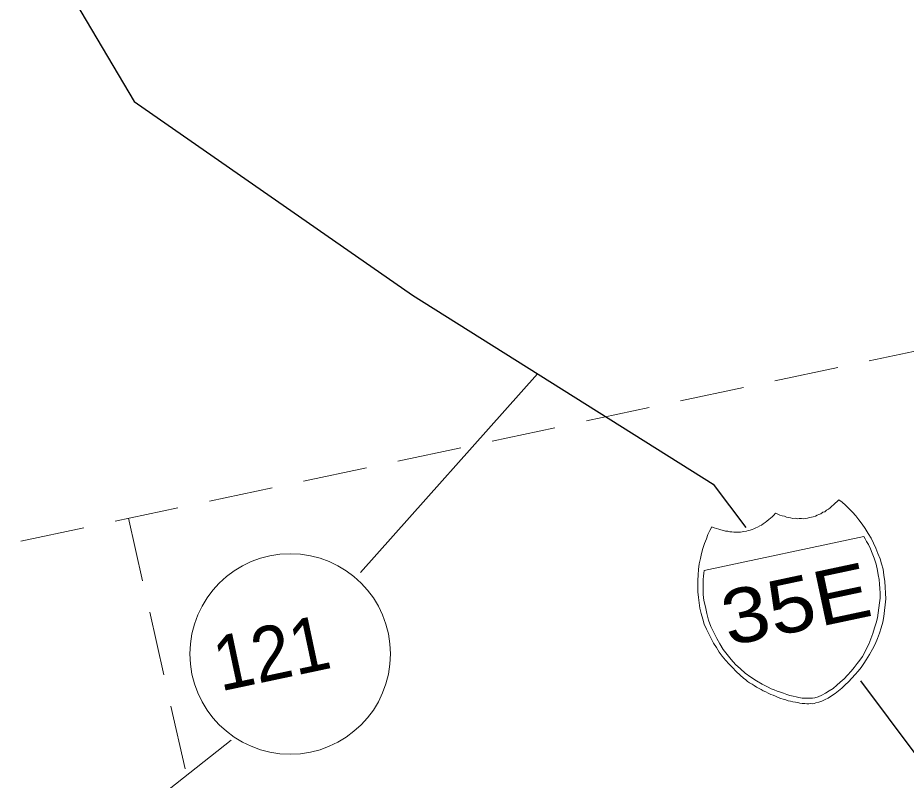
# Model space of a CAD drawing. Extents: x 2357218 to 2371708, y 6973728 to 6980157.
# Drawn here: x 2357598.1 to 2357681, y 6974819.3 to 6974890.5 of the extents above; entities that cross this region are included whole.
import ezdxf

# ---------------------------------------------------------------- set-up
doc = ezdxf.new("R2010")
doc.units = 0
doc.header["$LTSCALE"] = 2
doc.linetypes.add('MEDIUM_DASHED', pattern=[4.5, 3, -1.5])
doc.layers.add('62', color=7, linetype='Continuous', lineweight=13)
doc.layers.add('63', color=7, linetype='Continuous', lineweight=13)

msp = doc.modelspace()

# ---------------------------------------------------------------- linework, layer by layer
at = {"layer": '62', "linetype": 'MEDIUM_DASHED'}
for p, q in [((2357701.055, 6974863.476), (2357262.587, 6974770.278)), ((2357608.391, 6974843.78), (2357670.463, 6974569.716))]:
    msp.add_line(p, q, dxfattribs=at)
at = {"layer": '62'}
msp.add_line((2357630.08, 6974838.706), (2357646.606, 6974857.286), dxfattribs=at)
at = {"layer": '62', "lineweight": 25}
for points in [[(2357578.331, 6974934.355), (2357589.96, 6974914.697), (2357608.93, 6974882.704), (2357634.925, 6974864.627), (2357663.018, 6974846.971), (2357666.063, 6974842.928)], [(2357676.771, 6974828.593), (2357689.879, 6974811.067), (2357705.075, 6974777.351), (2357725.526, 6974754.738)]]:
    msp.add_lwpolyline(points, dxfattribs=at)
at = {"layer": '62'}
for points in [[(2357669.661, 6974843.969), (2357669.858, 6974843.896), (2357670.077, 6974843.85), (2357670.245, 6974843.817), (2357670.462, 6974843.771), (2357670.664, 6974843.789), (2357670.859, 6974843.739), (2357671.039, 6974843.756), (2357671.247, 6974843.752), (2357671.434, 6974843.747), (2357671.636, 6974843.766), (2357671.812, 6974843.804), (2357672.01, 6974843.845), (2357672.184, 6974843.882), (2357672.362, 6974843.92), (2357672.576, 6974843.99), (2357672.721, 6974844.067), (2357672.888, 6974844.148), (2357673.081, 6974844.213), (2357673.262, 6974844.341), (2357673.433, 6974844.402), (2357673.612, 6974844.532), (2357673.776, 6974844.635), (2357673.931, 6974844.762), (2357674.084, 6974844.909), (2357674.244, 6974845.035), (2357674.416, 6974845.185), (2357674.59, 6974845.337), (2357674.738, 6974845.508), (2357675.063, 6974845.278), (2357675.374, 6974844.999), (2357675.693, 6974844.697), (2357676.02, 6974844.354), (2357676.323, 6974844.005), (2357676.631, 6974843.632), (2357676.925, 6974843.234), (2357677.217, 6974842.837), (2357677.499, 6974842.367), (2357677.754, 6974841.938), (2357677.991, 6974841.46), (2357678.209, 6974840.979), (2357678.405, 6974840.491), (2357678.601, 6974840.003), (2357678.726, 6974839.522), (2357678.876, 6974839.026), (2357678.948, 6974838.467), (2357679.05, 6974837.889), (2357679.074, 6974837.342), (2357679.122, 6974836.8), (2357679.145, 6974836.252), (2357679.081, 6974835.686), (2357679.029, 6974835.168), (2357678.961, 6974834.624), (2357678.843, 6974834.094), (2357678.703, 6974833.558), (2357678.535, 6974833.061), (2357678.364, 6974832.566), (2357678.132, 6974832.033), (2357677.892, 6974831.545), (2357677.624, 6974831.074), (2357677.316, 6974830.57), (2357677.091, 6974830.225), (2357676.847, 6974829.85), (2357676.551, 6974829.512), (2357676.277, 6974829.178), (2357675.961, 6974828.834), (2357675.639, 6974828.512), (2357675.332, 6974828.216), (2357675.026, 6974827.923), (2357674.712, 6974827.673), (2357674.397, 6974827.422), (2357674.078, 6974827.192), (2357673.752, 6974826.984), (2357673.458, 6974826.854), (2357673.17, 6974826.699), (2357672.872, 6974826.591), (2357672.606, 6974826.534)], [(2357672.606, 6974826.534), (2357672.43, 6974826.497), (2357672.278, 6974826.463), (2357672.092, 6974826.47), (2357671.933, 6974826.458), (2357671.748, 6974826.466), (2357671.562, 6974826.474), (2357671.329, 6974826.492), (2357671.117, 6974826.516), (2357670.92, 6974826.567), (2357670.704, 6974826.613), (2357670.465, 6974826.653), (2357670.248, 6974826.699), (2357670.008, 6974826.741), (2357669.811, 6974826.813), (2357669.564, 6974826.899), (2357669.319, 6974826.963), (2357669.092, 6974827.053), (2357668.84, 6974827.161), (2357668.614, 6974827.25), (2357668.387, 6974827.338), (2357668.156, 6974827.452), (2357667.919, 6974827.585), (2357667.696, 6974827.676), (2357667.485, 6974827.791), (2357667.254, 6974827.904), (2357667.046, 6974828.02), (2357666.832, 6974828.159), (2357666.64, 6974828.302), (2357666.41, 6974828.415), (2357666.223, 6974828.534), (2357666.052, 6974828.682), (2357665.857, 6974828.849), (2357665.519, 6974829.143), (2357665.147, 6974829.48), (2357664.817, 6974829.847), (2357664.495, 6974830.17), (2357664.164, 6974830.536), (2357663.856, 6974830.906), (2357663.567, 6974831.284), (2357663.314, 6974831.713), (2357663.047, 6974832.114), (2357662.816, 6974832.55), (2357662.607, 6974832.99), (2357662.4, 6974833.43), (2357662.185, 6974833.89), (2357662.039, 6974834.365), (2357661.882, 6974834.885), (2357661.753, 6974835.385), (2357661.69, 6974835.901), (2357661.63, 6974836.395), (2357661.589, 6974836.916), (2357661.569, 6974837.442), (2357661.572, 6974837.97), (2357661.597, 6974838.505), (2357661.651, 6974838.999), (2357661.7, 6974839.539), (2357661.826, 6974840.025), (2357661.932, 6974840.508), (2357662.06, 6974840.971), (2357662.197, 6974841.416), (2357662.377, 6974841.868), (2357662.499, 6974842.262), (2357662.694, 6974842.647), (2357662.896, 6974842.991), (2357663.103, 6974842.896), (2357663.322, 6974842.827), (2357663.545, 6974842.761), (2357663.739, 6974842.71), (2357663.961, 6974842.64), (2357664.155, 6974842.592), (2357664.367, 6974842.567), (2357664.561, 6974842.517), (2357664.742, 6974842.533), (2357664.937, 6974842.482), (2357665.141, 6974842.501), (2357665.329, 6974842.494), (2357665.557, 6974842.498), (2357665.714, 6974842.508), (2357665.89, 6974842.546), (2357666.112, 6974842.593), (2357666.288, 6974842.63), (2357666.464, 6974842.667), (2357666.658, 6974842.732), (2357666.823, 6974842.813), (2357666.988, 6974842.893), (2357667.161, 6974842.955), (2357667.364, 6974843.09), (2357667.535, 6974843.149), (2357667.693, 6974843.272), (2357667.854, 6974843.378), (2357668.036, 6974843.507), (2357668.207, 6974843.66), (2357668.365, 6974843.785), (2357668.52, 6974843.933), (2357668.67, 6974844.08), (2357668.84, 6974844.254), (2357669.044, 6974844.159), (2357669.245, 6974844.087), (2357669.466, 6974844.019), (2357669.661, 6974843.969)], [(2357587.853, 6974800.146), (2357596.85, 6974808.683), (2357603.892, 6974811.906), (2357617.998, 6974823.047)]]:
    msp.add_lwpolyline(points, dxfattribs=at)
msp.add_lwpolyline([(2357677.08, 6974842.072), (2357662.176, 6974838.904), (2357662.137, 6974838.666), (2357662.106, 6974838.382), (2357662.083, 6974838.056), (2357662.084, 6974837.618), (2357662.068, 6974837.155), (2357662.082, 6974836.653), (2357662.154, 6974836.095), (2357662.283, 6974835.499), (2357662.41, 6974834.882), (2357662.588, 6974834.276), (2357662.807, 6974833.677), (2357663.064, 6974833.111), (2357663.341, 6974832.569), (2357663.634, 6974832.055), (2357663.953, 6974831.527), (2357664.332, 6974831.054), (2357664.706, 6974830.583), (2357665.099, 6974830.138), (2357665.554, 6974829.728), (2357666.009, 6974829.319), (2357666.526, 6974828.946), (2357667.06, 6974828.599), (2357667.586, 6974828.295), (2357668.153, 6974828.003), (2357668.417, 6974827.852), (2357668.715, 6974827.755), (2357668.993, 6974827.63), (2357669.312, 6974827.537), (2357669.587, 6974827.434), (2357669.889, 6974827.312), (2357670.181, 6974827.238), (2357670.473, 6974827.162), (2357670.76, 6974827.109), (2357671.027, 6974827.049), (2357671.312, 6974826.994), (2357671.549, 6974826.977), (2357671.825, 6974826.967), (2357672.054, 6974826.968), (2357672.284, 6974826.971), (2357672.508, 6974826.997), (2357672.806, 6974827.106), (2357673.168, 6974827.25), (2357673.496, 6974827.437), (2357673.861, 6974827.674), (2357674.206, 6974827.885), (2357674.554, 6974828.191), (2357674.883, 6974828.49), (2357675.233, 6974828.796), (2357675.573, 6974829.142), (2357675.887, 6974829.509), (2357676.181, 6974829.848), (2357676.452, 6974830.203), (2357676.724, 6974830.538), (2357676.951, 6974830.884), (2357677.158, 6974831.206), (2357677.279, 6974831.506), (2357677.537, 6974832.022), (2357677.729, 6974832.523), (2357677.923, 6974833.023), (2357678.087, 6974833.543), (2357678.241, 6974834.012), (2357678.345, 6974834.494), (2357678.432, 6974834.948), (2357678.493, 6974835.422), (2357678.554, 6974835.894), (2357678.603, 6974836.321), (2357678.595, 6974836.779), (2357678.573, 6974837.211), (2357678.55, 6974837.645), (2357678.504, 6974838.072), (2357678.437, 6974838.495), (2357678.35, 6974838.915), (2357678.223, 6974839.509), (2357678.062, 6974840.048), (2357677.869, 6974840.515), (2357677.71, 6974840.941), (2357677.512, 6974841.337), (2357677.337, 6974841.619), (2357677.193, 6974841.865)], close=True, dxfattribs=at)
msp.add_circle((2357623.504, 6974831.11), 9.364, dxfattribs=at)
at = {"layer": '63', "linetype": 'MEDIUM_DASHED'}
for p, q in [((2357701.055, 6974863.476), (2357262.587, 6974770.278)), ((2357608.391, 6974843.78), (2357670.463, 6974569.716))]:
    msp.add_line(p, q, dxfattribs=at)
at = {"layer": '63'}
msp.add_line((2357630.08, 6974838.706), (2357646.606, 6974857.286), dxfattribs=at)
at = {"layer": '63', "lineweight": 25}
for points in [[(2357578.331, 6974934.355), (2357589.96, 6974914.697), (2357608.93, 6974882.704), (2357634.925, 6974864.627), (2357663.018, 6974846.971), (2357666.063, 6974842.928)], [(2357676.771, 6974828.593), (2357689.879, 6974811.067), (2357705.075, 6974777.351), (2357725.526, 6974754.738)]]:
    msp.add_lwpolyline(points, dxfattribs=at)
at = {"layer": '63'}
for points in [[(2357669.661, 6974843.969), (2357669.858, 6974843.896), (2357670.077, 6974843.85), (2357670.245, 6974843.817), (2357670.462, 6974843.771), (2357670.664, 6974843.789), (2357670.859, 6974843.739), (2357671.039, 6974843.756), (2357671.247, 6974843.752), (2357671.434, 6974843.747), (2357671.636, 6974843.766), (2357671.812, 6974843.804), (2357672.01, 6974843.845), (2357672.184, 6974843.882), (2357672.362, 6974843.92), (2357672.576, 6974843.99), (2357672.721, 6974844.067), (2357672.888, 6974844.148), (2357673.081, 6974844.213), (2357673.262, 6974844.341), (2357673.433, 6974844.402), (2357673.612, 6974844.532), (2357673.776, 6974844.635), (2357673.931, 6974844.762), (2357674.084, 6974844.909), (2357674.244, 6974845.035), (2357674.416, 6974845.185), (2357674.59, 6974845.337), (2357674.738, 6974845.508), (2357675.063, 6974845.278), (2357675.374, 6974844.999), (2357675.693, 6974844.697), (2357676.02, 6974844.354), (2357676.323, 6974844.005), (2357676.631, 6974843.632), (2357676.925, 6974843.234), (2357677.217, 6974842.837), (2357677.499, 6974842.367), (2357677.754, 6974841.938), (2357677.991, 6974841.46), (2357678.209, 6974840.979), (2357678.405, 6974840.491), (2357678.601, 6974840.003), (2357678.726, 6974839.522), (2357678.876, 6974839.026), (2357678.948, 6974838.467), (2357679.05, 6974837.889), (2357679.074, 6974837.342), (2357679.122, 6974836.8), (2357679.145, 6974836.252), (2357679.081, 6974835.686), (2357679.029, 6974835.168), (2357678.961, 6974834.624), (2357678.843, 6974834.094), (2357678.703, 6974833.558), (2357678.535, 6974833.061), (2357678.364, 6974832.566), (2357678.132, 6974832.033), (2357677.892, 6974831.545), (2357677.624, 6974831.074), (2357677.316, 6974830.57), (2357677.091, 6974830.225), (2357676.847, 6974829.85), (2357676.551, 6974829.512), (2357676.277, 6974829.178), (2357675.961, 6974828.834), (2357675.639, 6974828.512), (2357675.332, 6974828.216), (2357675.026, 6974827.923), (2357674.712, 6974827.673), (2357674.397, 6974827.422), (2357674.078, 6974827.192), (2357673.752, 6974826.984), (2357673.458, 6974826.854), (2357673.17, 6974826.699), (2357672.872, 6974826.591), (2357672.606, 6974826.534)], [(2357672.606, 6974826.534), (2357672.43, 6974826.497), (2357672.278, 6974826.463), (2357672.092, 6974826.47), (2357671.933, 6974826.458), (2357671.748, 6974826.466), (2357671.562, 6974826.474), (2357671.329, 6974826.492), (2357671.117, 6974826.516), (2357670.92, 6974826.567), (2357670.704, 6974826.613), (2357670.465, 6974826.653), (2357670.248, 6974826.699), (2357670.008, 6974826.741), (2357669.811, 6974826.813), (2357669.564, 6974826.899), (2357669.319, 6974826.963), (2357669.092, 6974827.053), (2357668.84, 6974827.161), (2357668.614, 6974827.25), (2357668.387, 6974827.338), (2357668.156, 6974827.452), (2357667.919, 6974827.585), (2357667.696, 6974827.676), (2357667.485, 6974827.791), (2357667.254, 6974827.904), (2357667.046, 6974828.02), (2357666.832, 6974828.159), (2357666.64, 6974828.302), (2357666.41, 6974828.415), (2357666.223, 6974828.534), (2357666.052, 6974828.682), (2357665.857, 6974828.849), (2357665.519, 6974829.143), (2357665.147, 6974829.48), (2357664.817, 6974829.847), (2357664.495, 6974830.17), (2357664.164, 6974830.536), (2357663.856, 6974830.906), (2357663.567, 6974831.284), (2357663.314, 6974831.713), (2357663.047, 6974832.114), (2357662.816, 6974832.55), (2357662.607, 6974832.99), (2357662.4, 6974833.43), (2357662.185, 6974833.89), (2357662.039, 6974834.365), (2357661.882, 6974834.885), (2357661.753, 6974835.385), (2357661.69, 6974835.901), (2357661.63, 6974836.395), (2357661.589, 6974836.916), (2357661.569, 6974837.442), (2357661.572, 6974837.97), (2357661.597, 6974838.505), (2357661.651, 6974838.999), (2357661.7, 6974839.539), (2357661.826, 6974840.025), (2357661.932, 6974840.508), (2357662.06, 6974840.971), (2357662.197, 6974841.416), (2357662.377, 6974841.868), (2357662.499, 6974842.262), (2357662.694, 6974842.647), (2357662.896, 6974842.991), (2357663.103, 6974842.896), (2357663.322, 6974842.827), (2357663.545, 6974842.761), (2357663.739, 6974842.71), (2357663.961, 6974842.64), (2357664.155, 6974842.592), (2357664.367, 6974842.567), (2357664.561, 6974842.517), (2357664.742, 6974842.533), (2357664.937, 6974842.482), (2357665.141, 6974842.501), (2357665.329, 6974842.494), (2357665.557, 6974842.498), (2357665.714, 6974842.508), (2357665.89, 6974842.546), (2357666.112, 6974842.593), (2357666.288, 6974842.63), (2357666.464, 6974842.667), (2357666.658, 6974842.732), (2357666.823, 6974842.813), (2357666.988, 6974842.893), (2357667.161, 6974842.955), (2357667.364, 6974843.09), (2357667.535, 6974843.149), (2357667.693, 6974843.272), (2357667.854, 6974843.378), (2357668.036, 6974843.507), (2357668.207, 6974843.66), (2357668.365, 6974843.785), (2357668.52, 6974843.933), (2357668.67, 6974844.08), (2357668.84, 6974844.254), (2357669.044, 6974844.159), (2357669.245, 6974844.087), (2357669.466, 6974844.019), (2357669.661, 6974843.969)], [(2357587.853, 6974800.146), (2357596.85, 6974808.683), (2357603.892, 6974811.906), (2357617.998, 6974823.047)]]:
    msp.add_lwpolyline(points, dxfattribs=at)
msp.add_lwpolyline([(2357677.08, 6974842.072), (2357662.176, 6974838.904), (2357662.137, 6974838.666), (2357662.106, 6974838.382), (2357662.083, 6974838.056), (2357662.084, 6974837.618), (2357662.068, 6974837.155), (2357662.082, 6974836.653), (2357662.154, 6974836.095), (2357662.283, 6974835.499), (2357662.41, 6974834.882), (2357662.588, 6974834.276), (2357662.807, 6974833.677), (2357663.064, 6974833.111), (2357663.341, 6974832.569), (2357663.634, 6974832.055), (2357663.953, 6974831.527), (2357664.332, 6974831.054), (2357664.706, 6974830.583), (2357665.099, 6974830.138), (2357665.554, 6974829.728), (2357666.009, 6974829.319), (2357666.526, 6974828.946), (2357667.06, 6974828.599), (2357667.586, 6974828.295), (2357668.153, 6974828.003), (2357668.417, 6974827.852), (2357668.715, 6974827.755), (2357668.993, 6974827.63), (2357669.312, 6974827.537), (2357669.587, 6974827.434), (2357669.889, 6974827.312), (2357670.181, 6974827.238), (2357670.473, 6974827.162), (2357670.76, 6974827.109), (2357671.027, 6974827.049), (2357671.312, 6974826.994), (2357671.549, 6974826.977), (2357671.825, 6974826.967), (2357672.054, 6974826.968), (2357672.284, 6974826.971), (2357672.508, 6974826.997), (2357672.806, 6974827.106), (2357673.168, 6974827.25), (2357673.496, 6974827.437), (2357673.861, 6974827.674), (2357674.206, 6974827.885), (2357674.554, 6974828.191), (2357674.883, 6974828.49), (2357675.233, 6974828.796), (2357675.573, 6974829.142), (2357675.887, 6974829.509), (2357676.181, 6974829.848), (2357676.452, 6974830.203), (2357676.724, 6974830.538), (2357676.951, 6974830.884), (2357677.158, 6974831.206), (2357677.279, 6974831.506), (2357677.537, 6974832.022), (2357677.729, 6974832.523), (2357677.923, 6974833.023), (2357678.087, 6974833.543), (2357678.241, 6974834.012), (2357678.345, 6974834.494), (2357678.432, 6974834.948), (2357678.493, 6974835.422), (2357678.554, 6974835.894), (2357678.603, 6974836.321), (2357678.595, 6974836.779), (2357678.573, 6974837.211), (2357678.55, 6974837.645), (2357678.504, 6974838.072), (2357678.437, 6974838.495), (2357678.35, 6974838.915), (2357678.223, 6974839.509), (2357678.062, 6974840.048), (2357677.869, 6974840.515), (2357677.71, 6974840.941), (2357677.512, 6974841.337), (2357677.337, 6974841.619), (2357677.193, 6974841.865)], close=True, dxfattribs=at)
msp.add_circle((2357623.504, 6974831.11), 9.364, dxfattribs=at)

# ---------------------------------------------------------------- texts
at = {"layer": '62'}
for s, width, p in [('35E', 1.15, (2357664.439, 6974831.839)), ('121', 0.95, (2357616.984, 6974827.598))]:
    msp.add_text(s, height=5.099, rotation=12, dxfattribs=dict(at, width=width)).set_placement(p)
at = {"layer": '63'}
for s, width, p in [('35E', 1.15, (2357664.439, 6974831.839)), ('121', 0.95, (2357616.984, 6974827.598))]:
    msp.add_text(s, height=5.099, rotation=12, dxfattribs=dict(at, width=width)).set_placement(p)

doc.saveas('drawing.dxf')
